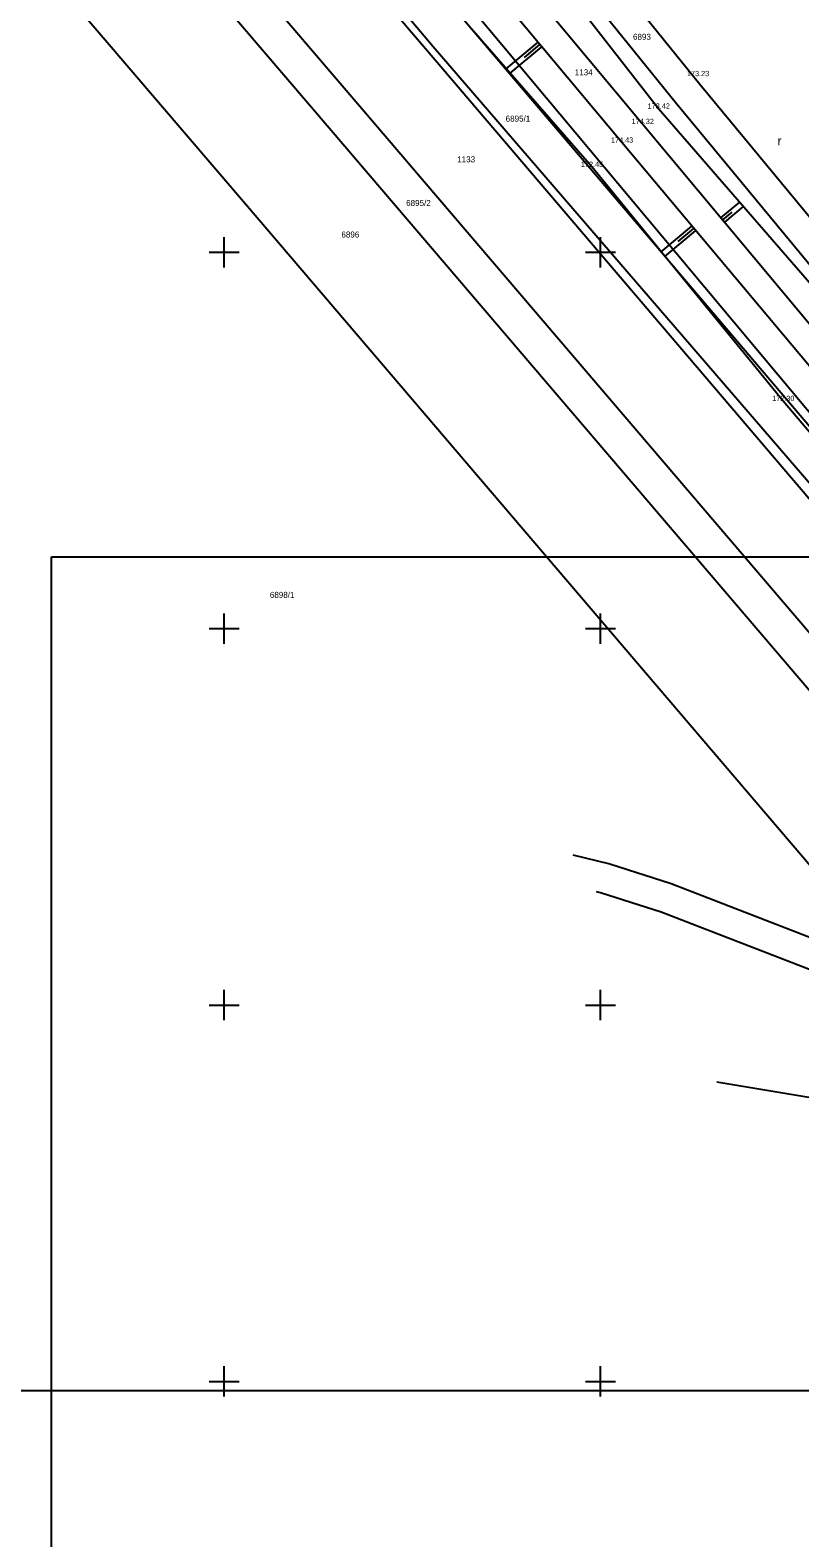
# Model space of a CAD drawing. Extents: x -612546 to -611926, y -1201932 to -1200444.
# Drawn here: x -612225.8 to -612123.5, y -1201270.8 to -1201070.5 of the extents above; entities that cross this region are included whole.
import ezdxf

# ---------------------------------------------------------------- set-up
doc = ezdxf.new("R2010")
doc.units = 0
for name, color, linetype in [('14 hrana pata svahu', 7, 'Continuous'), ('15 šrafy', 7, 'Continuous'), ('61 legenda křížky', 7, 'Continuous'), ('Hranice parcel', 7, 'Continuous'), ('Parcelní čísla', 7, 'Continuous'), ('Vnitřní kresba', 7, 'Continuous'), ('Vrstva 36', 7, 'Continuous'), ('Vrstva 63', 7, 'Continuous'), ('výška bodu', 7, 'Continuous')]:
    doc.layers.add(name, color=color, linetype=linetype)

msp = doc.modelspace()

# ---------------------------------------------------------------- linework, layer by layer
at = {"layer": '14 hrana pata svahu'}
for points in [[(-612115.84, -1201111.42), (-612142.3, -1201080.92), (-612162.58, -1201054.92), (-612187.22, -1201025.94), (-612211.45, -1200996.73), (-612237.71, -1200968.13), (-612275.47, -1200925.26), (-612297.25, -1200898.18), (-612305.42, -1200888.34), (-612310.59, -1200874.11), (-612323.74, -1200837.38), (-612336.44, -1200801.43), (-612350.12, -1200764.09), (-612361.57, -1200731.35), (-612377.95, -1200692.77), (-612388.38, -1200663.69), (-612401.66, -1200625.89), (-612414.44, -1200590.59), (-612427.78, -1200553.92), (-612436.33, -1200532.1), (-612442.76, -1200519.02), (-612455.83, -1200502.43), (-612463.71, -1200487.36), (-612471.87, -1200478.15)], [(-612103.83, -1201136.8), (-612121.3, -1201116.23), (-612147.17, -1201085.43), (-612168.95, -1201059.31), (-612192.84, -1201031.05), (-612217.78, -1201001.78), (-612242.41, -1200972.81), (-612279.4, -1200929.44), (-612302.66, -1200902.78), (-612311.18, -1200891.48), (-612317.69, -1200875.87), (-612330.64, -1200840.25), (-612343.46, -1200803.61), (-612356.83, -1200766.41), (-612369.51, -1200733.46), (-612383.93, -1200694.82), (-612394.68, -1200665.1), (-612407.78, -1200627.56), (-612420.74, -1200592.57), (-612433.93, -1200555.79), (-612441.34, -1200534.1), (-612447.31, -1200522.04), (-612459.97, -1200505.78), (-612472.95, -1200489.44)], [(-612100.62, -1201134.15), (-612118.63, -1201113.83), (-612144.42, -1201082.96), (-612165.7, -1201057.43), (-612190.2, -1201028.76), (-612215.18, -1200999.78), (-612240.07, -1200970.53), (-612277.47, -1200927.11), (-612299.67, -1200900.56), (-612307.52, -1200889.81), (-612314.18, -1200875.11), (-612327.34, -1200838.97)], [(-612083.4, -1201170.96), (-612107.88, -1201140.83), (-612125.72, -1201119.76), (-612151.16, -1201088.66), (-612173.22, -1201063.29), (-612197.5, -1201034.61), (-612222.4, -1201005.63), (-612247.09, -1200977.25), (-612284.99, -1200933.95), (-612307.37, -1200907.39), (-612317.17, -1200894.63), (-612323.51, -1200877.98), (-612336.33, -1200841.94)]]:
    msp.add_lwpolyline(points, dxfattribs=at)
at = {"layer": '15 šrafy'}
for p, q in [((-612162.5, -1201075.62), (-612158.28, -1201072.1)), ((-612161.97, -1201076.22), (-612157.77, -1201072.72)), ((-612160.07, -1201074.12), (-612158.03, -1201072.41)), ((-612131.54, -1201093.32), (-612134.03, -1201095.4)), ((-612132.55, -1201094.68), (-612133.77, -1201095.7)), ((-612131.02, -1201093.92), (-612133.52, -1201096.01)), ((-612141.94, -1201099.94), (-612137.86, -1201096.51)), ((-612139.67, -1201098.55), (-612137.6, -1201096.82)), ((-612141.43, -1201100.56), (-612137.35, -1201097.13))]:
    msp.add_line(p, q, dxfattribs=at)
at = {"layer": '61 legenda křížky'}
for p, q in [((-612200, -1201102), (-612200, -1201098)), ((-612150, -1201102), (-612150, -1201098)), ((-612202, -1201100), (-612198, -1201100)), ((-612152, -1201100), (-612148, -1201100)), ((-612200, -1201152), (-612200, -1201148)), ((-612150, -1201152), (-612150, -1201148)), ((-612202, -1201150), (-612198, -1201150)), ((-612152, -1201150), (-612148, -1201150)), ((-612200, -1201202), (-612200, -1201198)), ((-612150, -1201202), (-612150, -1201198)), ((-612202, -1201200), (-612198, -1201200)), ((-612152, -1201200), (-612148, -1201200)), ((-612200, -1201252), (-612200, -1201248)), ((-612150, -1201252), (-612150, -1201248)), ((-612202, -1201250), (-612198, -1201250)), ((-612152, -1201250), (-612148, -1201250))]:
    msp.add_line(p, q, dxfattribs=at)
at = {"layer": 'Hranice parcel'}
for points in [[(-612492.54, -1200475.45), (-612489.15, -1200479.9), (-612487.29, -1200482.34), (-612470.55, -1200499.86), (-612454.58, -1200517.89), (-612449.12, -1200526.98), (-612444.88, -1200537.01), (-612400.71, -1200658.68), (-612382.76, -1200708.97), (-612320.94, -1200880.21), (-612316.28, -1200891.06), (-612307.37, -1200903.62), (-612259.67, -1200958.71), (-612214.29, -1201012.03), (-612172.62, -1201060.98), (-612120.7, -1201123.05), (-612073.85, -1201178.4), (-612068.4, -1201184.83), (-612055.42, -1201199.11), (-612044.78, -1201213.9), (-612040.42, -1201224.33), (-612036.87, -1201232.26)], [(-612053.63, -1201234.04), (-612049.72, -1201229.74), (-612051.31, -1201220.57), (-612058.28, -1201208.42), (-612073.89, -1201189.58), (-612079.31, -1201183.16), (-612173.25, -1201072.99), (-612266.53, -1200963.98), (-612308.11, -1200916.05), (-612320.05, -1200901.46), (-612326.37, -1200888.91), (-612352.76, -1200817.26), (-612383.45, -1200732.24), (-612424.46, -1200618.96), (-612450.75, -1200547.77), (-612455.75, -1200534.91), (-612462.05, -1200524.68), (-612490.01, -1200492.58), (-612497.19, -1200482.99)], [(-612504.85, -1200495.41), (-612492.66, -1200506.93), (-612476.27, -1200525), (-612462.43, -1200549.41), (-612435.01, -1200623.69), (-612394.62, -1200736.44), (-612362.83, -1200822.52), (-612336.91, -1200893.7), (-612329.46, -1200906.86), (-612317.29, -1200922.46), (-612274.72, -1200972.15), (-612181.97, -1201080.59), (-612092.56, -1201185.28), (-612096.16, -1201188.77)], [(-612098.55, -1201185.97), (-612185.77, -1201083.84), (-612278.52, -1200975.4), (-612321.16, -1200925.63), (-612333.63, -1200909.64), (-612341.47, -1200895.8), (-612367.52, -1200824.24), (-612399.32, -1200738.15), (-612439.71, -1200625.4), (-612466.98, -1200551.52), (-612480.35, -1200527.95), (-612496.23, -1200510.43), (-612507.54, -1200499.75)], [(-612480.63, -1200557.86), (-612453.81, -1200630.53), (-612413.42, -1200743.28), (-612381.61, -1200829.41), (-612355.13, -1200902.11), (-612346.14, -1200918), (-612332.78, -1200935.12), (-612289.91, -1200985.15), (-612197.17, -1201093.58), (-612109.96, -1201195.71)], [(-612367.63, -1200702.46), (-612366.44, -1200717.27), (-612308.59, -1200877.88), (-612303.27, -1200888.65), (-612292.69, -1200901.79), (-612203.37, -1201003.51), (-612163.72, -1201050.75), (-612139.89, -1201080.24), (-612084.23, -1201147.54), (-612068.31, -1201163.86)], [(-612027.25, -1201146.78), (-612057.59, -1201153.91), (-612067.61, -1201153.97), (-612081.25, -1201144.86), (-612136.79, -1201077.71), (-612160.63, -1201048.21), (-612200.33, -1201000.9), (-612214.59, -1200984.67)], [(-612153.65, -1201180.06), (-612148.76, -1201181.25), (-612140.61, -1201183.84), (-612109.96, -1201195.71)], [(-612150.57, -1201184.92), (-612149.84, -1201185.1), (-612141.94, -1201187.61), (-612106.9, -1201201.18), (-612098.37, -1201202.51), (-612085.58, -1201201.15)], [(-612134.54, -1201210.22), (-612061.86, -1201222.29)]]:
    msp.add_lwpolyline(points, dxfattribs=at)
at = {"layer": 'Vnitřní kresba'}
msp.add_line((-612174.91, -1201061.11), (-612079.46, -1201173.47), dxfattribs=at)
msp.add_lwpolyline([(-612077.99, -1201182.01), (-612172.2, -1201072.72), (-612264.55, -1200963.36), (-612306.48, -1200914.97), (-612319.15, -1200900.26), (-612324.5, -1200887.86), (-612350.35, -1200818.69), (-612381.6, -1200731.97), (-612422.84, -1200618.87), (-612449.81, -1200544.11), (-612465.28, -1200517.45), (-612482.79, -1200495.64), (-612497.19, -1200482.99)], dxfattribs=at)
at = {"layer": 'Vrstva 63'}
for p, q in [((-612222.92, -1201560.45), (-612222.92, -1201140.45)), ((-612222.92, -1201140.45), (-611925.92, -1201140.45)), ((-612062.93, -1201251.26), (-612359.93, -1201251.26))]:
    msp.add_line(p, q, dxfattribs=at)

# ---------------------------------------------------------------- texts
at = {"layer": 'Parcelní čísla'}
for s, p in [('6893', (-612145.67, -1201071.77)), ('1134', (-612153.41, -1201076.49)), ('6895/1', (-612162.59, -1201082.64)), ('1133', (-612169.03, -1201088.05)), ('6895/2', (-612175.81, -1201093.85)), ('6896', (-612184.41, -1201098.04)), ('6898/1', (-612193.92, -1201145.91))]:
    msp.add_text(s, height=0.8, dxfattribs=at).set_placement(p)
at = {"layer": 'Vrstva 36'}
msp.add_text('r', height=1.2, dxfattribs=at).set_placement((-612126.46, -1201085.8))
at = {"layer": 'výška bodu'}
for s, p in [('173.23', (-612138.5, -1201076.6)), ('173.42', (-612143.73, -1201080.92)), ('174.32', (-612145.85, -1201082.96)), ('174.43', (-612148.6, -1201085.43)), ('172.45', (-612152.59, -1201088.66)), ('172.30', (-612127.18, -1201119.76))]:
    msp.add_text(s, height=0.7, dxfattribs=at).set_placement(p)

doc.saveas('drawing.dxf')
